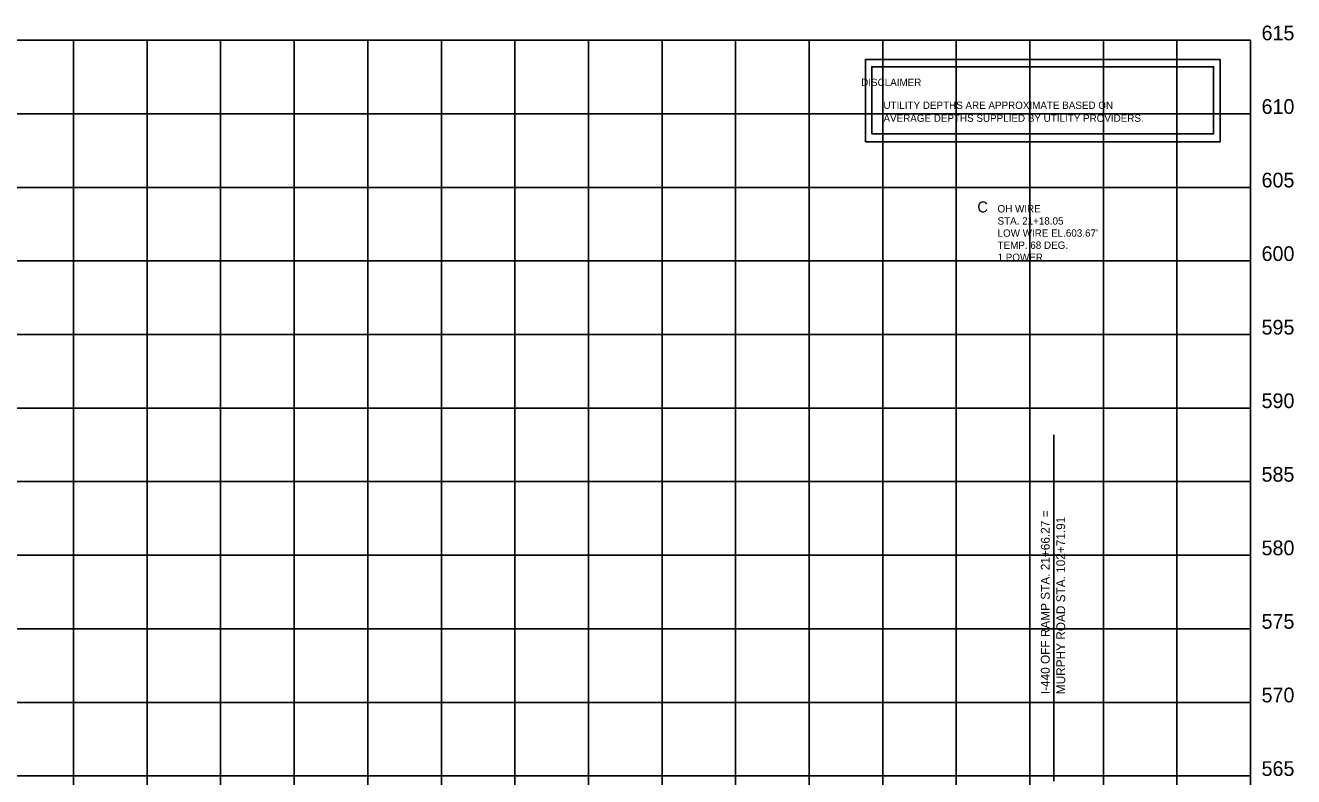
# Model space of a CAD drawing. Extents: x 1724534 to 1727318, y 657156 to 660047.
# Drawn here: x 1726456 to 1727318, y 657727 to 658238 of the extents above; entities that cross this region are included whole.
import ezdxf

# ---------------------------------------------------------------- set-up
doc = ezdxf.new("R2010")
doc.units = 0
for name, color, linetype in [('DESIGN - SHEET - Corner Text', 7, 'Continuous'), ('DESIGN - SHEET - Light Grid', 7, 'Continuous'), ('SURVEY - PROFILE - Ground Line with Text', 7, 'Continuous'), ('SURVEY - PROFILE - Utilities - Overhead Wire Crossings', 7, 'Continuous'), ('SURVEY - UTILITIES - Owners', 7, 'Continuous')]:
    doc.layers.add(name, color=color, linetype=linetype)

msp = doc.modelspace()

# ---------------------------------------------------------------- linework, layer by layer
at = {"layer": 'DESIGN - SHEET - Light Grid'}
for p, q in [((1727288.59, 658227.62), (1725888.59, 658227.62)), ((1726488.59, 657227.62), (1726488.59, 658227.62)), ((1726538.59, 657227.62), (1726538.59, 658227.62)), ((1726588.59, 657227.62), (1726588.59, 658227.62)), ((1726638.59, 657227.62), (1726638.59, 658227.62)), ((1726688.59, 657227.62), (1726688.59, 658227.62)), ((1726738.59, 657227.62), (1726738.59, 658227.62)), ((1726788.59, 657227.62), (1726788.59, 658227.62)), ((1726838.59, 657227.62), (1726838.59, 658227.62)), ((1726888.59, 657227.62), (1726888.59, 658227.62)), ((1726938.59, 657227.62), (1726938.59, 658227.62)), ((1726988.59, 657227.62), (1726988.59, 658227.62)), ((1727038.59, 657227.62), (1727038.59, 658227.62)), ((1727088.59, 657227.62), (1727088.59, 658227.62)), ((1727138.59, 657227.62), (1727138.59, 658227.62)), ((1727188.59, 657227.62), (1727188.59, 658227.62)), ((1727238.59, 657227.62), (1727238.59, 658227.62)), ((1727288.59, 657227.62), (1727288.59, 658227.62)), ((1725888.59, 658177.62), (1727288.59, 658177.62)), ((1725888.59, 658127.62), (1727288.59, 658127.62)), ((1725888.59, 658077.62), (1727288.59, 658077.62)), ((1725888.59, 658027.62), (1727288.59, 658027.62)), ((1725888.59, 657977.62), (1727288.59, 657977.62)), ((1725888.59, 657927.62), (1727288.59, 657927.62)), ((1725888.59, 657877.62), (1727288.59, 657877.62)), ((1725888.59, 657827.62), (1727288.59, 657827.62)), ((1725888.59, 657777.62), (1727288.59, 657777.62)), ((1725888.59, 657727.62), (1727288.59, 657727.62))]:
    msp.add_line(p, q, dxfattribs=at)
at = {"layer": 'SURVEY - PROFILE - Ground Line with Text'}
msp.add_line((1727154.85, 657724.04), (1727154.85, 657959.41), dxfattribs=at)
at = {"layer": 'SURVEY - UTILITIES - Owners'}
for points in [[(1727026.8, 658158.69), (1727026.8, 658214.51), (1727267.99, 658214.51), (1727267.99, 658158.69)], [(1727031.15, 658164.11), (1727031.15, 658209.67), (1727263.48, 658209.67), (1727263.48, 658164.11)]]:
    msp.add_lwpolyline(points, close=True, dxfattribs=at)

# ---------------------------------------------------------------- texts
at = {"layer": 'DESIGN - SHEET - Corner Text'}
for s, p in [('615', (1727296.09, 658227.62)), ('610', (1727296.09, 658177.62)), ('605', (1727296.09, 658127.62)), ('600', (1727296.09, 658077.62)), ('595', (1727296.09, 658027.62)), ('590', (1727296.09, 657977.62)), ('585', (1727296.09, 657927.62)), ('580', (1727296.09, 657877.62)), ('575', (1727296.09, 657827.62)), ('570', (1727296.09, 657777.62)), ('565', (1727296.09, 657727.62))]:
    msp.add_text(s, height=10, dxfattribs=at).set_placement(p)
at = {"layer": 'SURVEY - PROFILE - Ground Line with Text'}
for s, p in [('I-440 OFF RAMP STA. 21+66.27 =', (1727152.08, 657783.17)), ('MURPHY ROAD STA. 102+71.91', (1727162.58, 657783.17))]:
    msp.add_text(s, height=6, rotation=90, dxfattribs=at).set_placement(p)
at = {"layer": 'SURVEY - PROFILE - Utilities - Overhead Wire Crossings'}
for s, height, p in [('C', 7.5, (1727102.89, 658110.6)), ('OH WIRE', 5, (1727116.64, 658110.6)), ('STA. 21+18.05', 5, (1727116.64, 658102.35)), ("LOW WIRE EL.603.67'", 5, (1727116.64, 658094.1)), ('TEMP. 68 DEG.', 5, (1727116.64, 658085.85)), ('1 POWER', 5, (1727116.64, 658077.6))]:
    msp.add_text(s, height=height, dxfattribs=at).set_placement(p)
at = {"layer": 'SURVEY - UTILITIES - Owners'}
for s, p in [('                             DISCLAIMER', (1726970.09, 658196.52)), ('UTILITY DEPTHS ARE APPROXIMATE BASED ON', (1727039.11, 658180.96)), ('AVERAGE DEPTHS SUPPLIED BY UTILITY PROVIDERS.', (1727039.11, 658172.21))]:
    msp.add_text(s, height=5, dxfattribs=at).set_placement(p)

doc.saveas('drawing.dxf')
